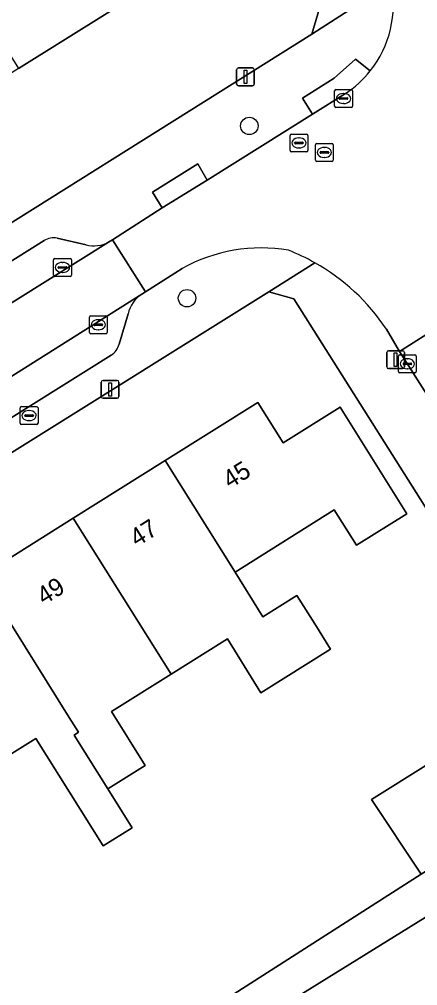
# Model space of a CAD drawing. Extents: x 159352 to 160617, y 385888 to 387323.
# Drawn here: x 159710.7 to 159733, y 386029 to 386083.1 of the extents above; entities that cross this region are included whole.
import ezdxf

# ---------------------------------------------------------------- set-up
doc = ezdxf.new("R2010")
doc.units = 0
for name, color, linetype in [('IMGEO_Boom', 7, 'Continuous'), ('IMGEO_Brandkraan', 7, 'Continuous'), ('IMGEO_Erf', 7, 'Continuous'), ('IMGEO_Kolk', 7, 'Continuous'), ('IMGEO_Lichtmast', 7, 'Continuous'), ('IMGEO_Muur', 7, 'Continuous'), ('IMGEO_Pand', 7, 'Continuous'), ('IMGEO_Pand_nummerreeks', 7, 'Continuous'), ('IMGEO_Parkeervlak_open', 7, 'Continuous'), ('IMGEO_Rijbaan_lokaal_open', 7, 'Continuous'), ('IMGEO_Rioolput', 7, 'Continuous'), ('IMGEO_Voetpad_open', 7, 'Continuous')]:
    doc.layers.add(name, color=color, linetype=linetype)

msp = doc.modelspace()

# ---------------------------------------------------------------- linework, layer by layer
at = {"layer": 'IMGEO_Boom'}
for centre in [(159723.56, 386077.111), (159720.07, 386067.462)]:
    msp.add_circle(centre, 0.489, dxfattribs=at)
at = {"layer": 'IMGEO_Brandkraan'}
for p, q in [((159710.714, 386060.464), (159710.714, 386061.316)), ((159710.789, 386061.39), (159711.641, 386061.39)), ((159711.715, 386061.316), (159711.715, 386060.464)), ((159710.973, 386060.884), (159710.973, 386060.896)), ((159711.411, 386060.847), (159711.013, 386060.847)), ((159711.016, 386060.933), (159711.414, 386060.933)), ((159711.202, 386061.17), (159711.227, 386061.17)), ((159711.457, 386060.896), (159711.457, 386060.884)), ((159711.641, 386060.39), (159710.789, 386060.39)), ((159711.225, 386060.61), (159711.2, 386060.61))]:
    msp.add_line(p, q, dxfattribs=at)
for points in [[(159710.714, 386060.464), (159710.714, 386061.316)], [(159710.789, 386061.39), (159711.641, 386061.39)], [(159711.715, 386061.316), (159711.715, 386060.464)], [(159711.641, 386060.39), (159710.789, 386060.39)]]:
    msp.add_lwpolyline(points, dxfattribs=at)
for centre, radius, start, end in [((159710.791, 386061.314), 0.0765, 91.552, 178.448), ((159710.791, 386061.314), 0.0765, 91.552, 178.448), ((159711.639, 386061.314), 0.0765, 1.552, 88.448), ((159711.639, 386061.314), 0.0765, 1.552, 88.448), ((159711.013, 386060.893), 0.0403, 85.8775, 175.7526), ((159711.01, 386060.883), 0.0366, 178.938, 274.7102), ((159711.414, 386060.89), 0.043, 264.8664, 352.4533), ((159711.418, 386060.895), 0.0386, 1.7309, 96.639), ((159710.791, 386060.466), 0.0765, 181.552, 268.448), ((159710.791, 386060.466), 0.0765, 181.552, 268.448), ((159711.639, 386060.466), 0.0765, 271.552, 358.448), ((159711.639, 386060.466), 0.0765, 271.552, 358.448)]:
    msp.add_arc(centre, radius, start, end, dxfattribs=at)
for centre, major_axis, ratio, start_param, end_param in [((159711.201, 386060.89), (-0.387, 0.002), 0.722429, 4.712389, 7.853982), ((159711.226, 386060.89), (-0.39, 0.002), 0.717154, 1.570796, 4.712389)]:
    msp.add_ellipse(centre, major_axis=major_axis, ratio=ratio, start_param=start_param, end_param=end_param, dxfattribs=at)
at = {"layer": 'IMGEO_Erf'}
for points in [[(159682.021, 386086.971), (159675.765, 386083.062), (159677.645, 386080.051), (159675.693, 386078.833), (159673.743, 386077.616), (159671.864, 386080.628), (159664.171, 386075.803), (159675.622, 386057.544), (159678.147, 386053.368), (159680.364, 386052.973), (159727.06, 386082.254), (159727.834, 386084.857)], [(159715.741, 386083.528), (159710.62, 386080.324), (159705.257, 386076.97), (159700.341, 386073.894), (159694.987, 386070.545), (159689.802, 386067.302), (159684.835, 386064.194), (159679.316, 386060.742), (159677.344, 386063.895), (159674.183, 386061.917), (159668.443, 386071.26), (159671.836, 386073.379), (159671.913, 386073.256), (159673.873, 386070.118), (159679.098, 386073.381), (159679.277, 386073.094), (159684.247, 386076.198), (159689.434, 386079.437), (159694.775, 386082.772), (159696.55, 386079.963), (159701.469, 386083.035), (159701.464, 386083.043), (159699.747, 386085.796)], [(159708.502, 386051.905), (159713.682, 386055.143), (159718.85, 386058.374), (159724.039, 386061.618), (159725.451, 386059.359), (159728.653, 386061.361), (159732.387, 386055.393), (159729.564, 386053.627), (159728.326, 386055.605), (159722.758, 386052.122), (159724.32, 386049.624), (159726.229, 386050.819), (159727.228, 386049.223), (159728.112, 386047.81), (159724.213, 386045.369), (159722.329, 386048.377), (159719.171, 386046.4), (159715.841, 386044.315), (159717.73, 386041.298), (159715.63, 386039.982), (159716.992, 386037.806), (159715.372, 386036.791), (159711.6, 386042.813), (159708.294, 386040.745)]]:
    msp.add_lwpolyline(points, dxfattribs=at)
msp.add_lwpolyline([(159733.186, 386035.211), (159730.405, 386039.383), (159739.998, 386045.377), (159726.053, 386067.427), (159724.652, 386067.823), (159682.76, 386041.661), (159677.195, 386038.177), (159676.499, 386035.726), (159692.861, 386009.756), (159693.588, 386010.224), (159695.905, 386011.714), (159692.99, 386016.431), (159699.422, 386020.406), (159702.337, 386015.688), (159707.722, 386019.015), (159705.988, 386021.823), (159710.701, 386024.734), (159712.435, 386021.927)], close=True, dxfattribs=at)
at = {"layer": 'IMGEO_Kolk'}
for p, q in [((159728.418, 386079.147), (159729.27, 386079.147)), ((159728.343, 386078.221), (159728.343, 386079.073)), ((159728.602, 386078.641), (159728.602, 386078.653)), ((159729.04, 386078.604), (159728.642, 386078.604)), ((159728.645, 386078.69), (159729.043, 386078.69)), ((159728.831, 386078.927), (159728.856, 386078.927)), ((159729.086, 386078.653), (159729.086, 386078.641)), ((159729.344, 386079.073), (159729.344, 386078.221)), ((159729.27, 386078.147), (159728.418, 386078.147)), ((159728.854, 386078.367), (159728.829, 386078.367)), ((159712.586, 386068.76), (159712.586, 386069.612)), ((159712.661, 386069.686), (159713.513, 386069.686)), ((159713.074, 386069.466), (159713.099, 386069.466)), ((159713.587, 386069.612), (159713.587, 386068.76)), ((159712.845, 386069.18), (159712.845, 386069.192)), ((159713.283, 386069.143), (159712.885, 386069.143)), ((159712.888, 386069.229), (159713.286, 386069.229)), ((159713.097, 386068.906), (159713.072, 386068.906)), ((159713.329, 386069.192), (159713.329, 386069.18)), ((159713.513, 386068.686), (159712.661, 386068.686)), ((159714.595, 386065.55), (159714.595, 386066.402)), ((159714.67, 386066.476), (159715.522, 386066.476)), ((159715.083, 386066.256), (159715.108, 386066.256)), ((159715.596, 386066.402), (159715.596, 386065.55)), ((159714.854, 386065.97), (159714.854, 386065.982)), ((159715.292, 386065.933), (159714.894, 386065.933)), ((159714.897, 386066.019), (159715.295, 386066.019)), ((159715.106, 386065.696), (159715.081, 386065.696)), ((159715.338, 386065.982), (159715.338, 386065.97)), ((159715.522, 386065.476), (159714.67, 386065.476)), ((159731.919, 386063.363), (159731.919, 386064.215)), ((159731.994, 386064.289), (159732.846, 386064.289)), ((159732.407, 386064.069), (159732.432, 386064.069)), ((159732.92, 386064.215), (159732.92, 386063.363)), ((159732.178, 386063.783), (159732.178, 386063.795)), ((159732.616, 386063.746), (159732.218, 386063.746)), ((159732.221, 386063.832), (159732.619, 386063.832)), ((159732.43, 386063.509), (159732.405, 386063.509)), ((159732.662, 386063.795), (159732.662, 386063.783)), ((159732.846, 386063.289), (159731.994, 386063.289))]:
    msp.add_line(p, q, dxfattribs=at)
for points in [[(159728.418, 386079.147), (159729.27, 386079.147)], [(159728.343, 386078.221), (159728.343, 386079.073)], [(159729.344, 386079.073), (159729.344, 386078.221)], [(159729.27, 386078.147), (159728.418, 386078.147)], [(159712.586, 386068.76), (159712.586, 386069.612)], [(159712.661, 386069.686), (159713.513, 386069.686)], [(159713.587, 386069.612), (159713.587, 386068.76)], [(159713.513, 386068.686), (159712.661, 386068.686)], [(159714.595, 386065.55), (159714.595, 386066.402)], [(159714.67, 386066.476), (159715.522, 386066.476)], [(159715.596, 386066.402), (159715.596, 386065.55)], [(159715.522, 386065.476), (159714.67, 386065.476)], [(159731.919, 386063.363), (159731.919, 386064.215)], [(159731.994, 386064.289), (159732.846, 386064.289)], [(159732.92, 386064.215), (159732.92, 386063.363)], [(159732.846, 386063.289), (159731.994, 386063.289)]]:
    msp.add_lwpolyline(points, dxfattribs=at)
for centre, radius, start, end in [((159728.42, 386079.071), 0.0765, 91.552, 178.448), ((159728.42, 386079.071), 0.0765, 91.552, 178.448), ((159729.268, 386079.071), 0.0765, 1.552, 88.448), ((159729.268, 386079.071), 0.0765, 1.552, 88.448), ((159728.642, 386078.65), 0.0403, 85.8775, 175.7526), ((159728.639, 386078.64), 0.0366, 178.938, 274.7102), ((159729.043, 386078.647), 0.043, 264.8664, 352.4533), ((159729.047, 386078.652), 0.0386, 1.7309, 96.639), ((159728.42, 386078.223), 0.0765, 181.552, 268.448), ((159728.42, 386078.223), 0.0765, 181.552, 268.448), ((159729.268, 386078.223), 0.0765, 271.552, 358.448), ((159729.268, 386078.223), 0.0765, 271.552, 358.448), ((159712.663, 386069.61), 0.0765, 91.552, 178.448), ((159712.663, 386069.61), 0.0765, 91.552, 178.448), ((159713.511, 386069.61), 0.0765, 1.552, 88.448), ((159713.511, 386069.61), 0.0765, 1.552, 88.448), ((159712.885, 386069.189), 0.0403, 85.8775, 175.7526), ((159712.882, 386069.179), 0.0366, 178.938, 274.7102), ((159713.286, 386069.186), 0.043, 264.8664, 352.4533), ((159713.29, 386069.191), 0.0386, 1.7309, 96.639), ((159712.663, 386068.762), 0.0765, 181.552, 268.448), ((159712.663, 386068.762), 0.0765, 181.552, 268.448), ((159713.511, 386068.762), 0.0765, 271.552, 358.448), ((159713.511, 386068.762), 0.0765, 271.552, 358.448), ((159714.672, 386066.4), 0.0765, 91.552, 178.448), ((159714.672, 386066.4), 0.0765, 91.552, 178.448), ((159715.52, 386066.4), 0.0765, 1.552, 88.448), ((159715.52, 386066.4), 0.0765, 1.552, 88.448), ((159714.894, 386065.979), 0.0403, 85.8775, 175.7526), ((159714.891, 386065.969), 0.0366, 178.938, 274.7102), ((159715.295, 386065.976), 0.043, 264.8664, 352.4533), ((159715.299, 386065.981), 0.0386, 1.7309, 96.639), ((159714.672, 386065.552), 0.0765, 181.552, 268.448), ((159714.672, 386065.552), 0.0765, 181.552, 268.448), ((159715.52, 386065.552), 0.0765, 271.552, 358.448), ((159715.52, 386065.552), 0.0765, 271.552, 358.448), ((159731.996, 386064.213), 0.0765, 91.552, 178.448), ((159731.996, 386064.213), 0.0765, 91.552, 178.448), ((159732.844, 386064.213), 0.0765, 1.552, 88.448), ((159732.844, 386064.213), 0.0765, 1.552, 88.448), ((159732.218, 386063.792), 0.0403, 85.8775, 175.7526), ((159732.215, 386063.782), 0.0366, 178.938, 274.7102), ((159732.619, 386063.789), 0.043, 264.8664, 352.4533), ((159732.623, 386063.794), 0.0386, 1.7309, 96.639), ((159731.996, 386063.365), 0.0765, 181.552, 268.448), ((159731.996, 386063.365), 0.0765, 181.552, 268.448), ((159732.844, 386063.365), 0.0765, 271.552, 358.448), ((159732.844, 386063.365), 0.0765, 271.552, 358.448)]:
    msp.add_arc(centre, radius, start, end, dxfattribs=at)
for centre, major_axis, ratio, start_param, end_param in [((159728.83, 386078.647), (-0.387, 0.002), 0.722429, 4.712389, 7.853982), ((159728.855, 386078.647), (-0.39, 0.002), 0.717154, 1.570796, 4.712389), ((159713.073, 386069.186), (-0.387, 0.002), 0.722429, 4.712389, 7.853982), ((159713.098, 386069.186), (-0.39, 0.002), 0.717154, 1.570796, 4.712389), ((159715.082, 386065.976), (-0.387, 0.002), 0.722429, 4.712389, 7.853982), ((159715.107, 386065.976), (-0.39, 0.002), 0.717154, 1.570796, 4.712389), ((159732.406, 386063.789), (-0.387, 0.002), 0.722429, 4.712389, 7.853982), ((159732.431, 386063.789), (-0.39, 0.002), 0.717154, 1.570796, 4.712389)]:
    msp.add_ellipse(centre, major_axis=major_axis, ratio=ratio, start_param=start_param, end_param=end_param, dxfattribs=at)
at = {"layer": 'IMGEO_Lichtmast'}
for p, q in [((159722.845, 386079.457), (159722.845, 386080.257)), ((159722.845, 386080.257), (159722.845, 386079.457)), ((159722.945, 386080.357), (159723.735, 386080.357)), ((159723.735, 386080.357), (159722.945, 386080.357)), ((159723.835, 386080.257), (159723.835, 386079.457)), ((159723.835, 386079.457), (159723.835, 386080.257)), ((159723.735, 386079.357), (159722.945, 386079.357)), ((159722.945, 386079.357), (159723.735, 386079.357)), ((159731.36, 386064.52), (159732.15, 386064.52)), ((159732.15, 386064.52), (159731.36, 386064.52)), ((159731.26, 386063.62), (159731.26, 386064.42)), ((159731.26, 386064.42), (159731.26, 386063.62)), ((159732.25, 386064.42), (159732.25, 386063.62)), ((159732.25, 386063.62), (159732.25, 386064.42)), ((159732.15, 386063.52), (159731.36, 386063.52)), ((159731.36, 386063.52), (159732.15, 386063.52)), ((159715.365, 386062.857), (159716.155, 386062.857)), ((159716.155, 386062.857), (159715.365, 386062.857)), ((159715.265, 386061.957), (159715.265, 386062.757)), ((159715.265, 386062.757), (159715.265, 386061.957)), ((159716.255, 386062.757), (159716.255, 386061.957)), ((159716.255, 386061.957), (159716.255, 386062.757)), ((159716.155, 386061.857), (159715.365, 386061.857)), ((159715.365, 386061.857), (159716.155, 386061.857))]:
    msp.add_line(p, q, dxfattribs=at)
for points in [[(159723.265, 386080.232), (159723.415, 386080.232), (159723.415, 386079.482), (159723.265, 386079.482), (159723.265, 386080.232)], [(159731.68, 386064.395), (159731.83, 386064.395), (159731.83, 386063.645), (159731.68, 386063.645), (159731.68, 386064.395)], [(159715.685, 386062.732), (159715.835, 386062.732), (159715.835, 386061.982), (159715.685, 386061.982), (159715.685, 386062.732)]]:
    msp.add_lwpolyline(points, dxfattribs=at)
for centre, start, end in [((159722.945, 386080.257), 90, 180), ((159722.945, 386080.257), 90, 180), ((159723.735, 386080.257), 0, 90), ((159723.735, 386080.257), 360, 90), ((159722.945, 386079.457), 180, 270), ((159722.945, 386079.457), 180, 270), ((159723.735, 386079.457), 270, 0), ((159723.735, 386079.457), 270, 0), ((159731.36, 386064.42), 90, 180), ((159731.36, 386064.42), 90, 180), ((159732.15, 386064.42), 0, 90), ((159732.15, 386064.42), 360, 90), ((159731.36, 386063.62), 180, 270), ((159731.36, 386063.62), 180, 270), ((159732.15, 386063.62), 270, 0), ((159732.15, 386063.62), 270, 0), ((159715.365, 386062.757), 90, 180), ((159715.365, 386062.757), 90, 180), ((159716.155, 386062.757), 0, 90), ((159716.155, 386062.757), 360, 90), ((159715.365, 386061.957), 180, 270), ((159715.365, 386061.957), 180, 270), ((159716.155, 386061.957), 270, 0), ((159716.155, 386061.957), 270, 0)]:
    msp.add_arc(centre, 0.1, start, end, dxfattribs=at)
at = {"layer": 'IMGEO_Muur'}
msp.add_lwpolyline([(159739.998, 386045.377), (159726.053, 386067.427)], dxfattribs=at)
at = {"layer": 'IMGEO_Pand'}
for points in [[(159710.256, 386092.311), (159705.178, 386089.14), (159705.249, 386089.026), (159706.834, 386086.386), (159710.62, 386080.324), (159715.741, 386083.528)], [(159722.758, 386052.122), (159728.326, 386055.605), (159729.564, 386053.627), (159732.387, 386055.393), (159728.653, 386061.361), (159725.451, 386059.359), (159724.039, 386061.618), (159718.85, 386058.374)], [(159724.32, 386049.624), (159722.758, 386052.122), (159718.85, 386058.374), (159713.682, 386055.143), (159719.171, 386046.4), (159722.329, 386048.377), (159724.213, 386045.369), (159728.112, 386047.81), (159727.228, 386049.223), (159726.229, 386050.819)], [(159713.682, 386055.143), (159708.502, 386051.905), (159713.466, 386043.98), (159713.984, 386043.152), (159713.74, 386042.999), (159715.63, 386039.982), (159717.73, 386041.298), (159715.841, 386044.315), (159719.171, 386046.4)], [(159708.502, 386051.905), (159703.328, 386048.671), (159707.246, 386042.417), (159708.294, 386040.745), (159711.6, 386042.813), (159715.372, 386036.791), (159716.992, 386037.806), (159715.63, 386039.982), (159713.74, 386042.999), (159713.984, 386043.152), (159713.466, 386043.98)], [(159739.998, 386045.377), (159730.405, 386039.383), (159733.186, 386035.211), (159742.641, 386041.129)]]:
    msp.add_lwpolyline(points, close=True, dxfattribs=at)
at = {"layer": 'IMGEO_Parkeervlak_open'}
for points in [[(159684.747, 386051.268), (159715.668, 386070.601)], [(159712.06, 386070.688), (159686.23, 386054.518)], [(159714.408, 386070.453), (159712.791, 386070.822)], [(159717.543, 386067.695), (159686.194, 386047.956), (159678.382, 386043.037)], [(159716.265, 386064.895), (159716.765, 386066.587)], [(159681.467, 386042.865), (159702.746, 386056.105), (159715.811, 386064.272)]]:
    msp.add_lwpolyline(points, dxfattribs=at)
for centre, radius, start, end in [((159712.594, 386069.835), 1.006, 78.7215, 122.0536), ((159714.846, 386072.164), 1.766, 255.6525, 297.7461), ((159718.52, 386066.182), 1.801, 122.8468, 167.0028), ((159715.242, 386065.164), 1.058, 302.5514, 345.2845)]:
    msp.add_arc(centre, radius, start, end, dxfattribs=at)
at = {"layer": 'IMGEO_Rijbaan_lokaal_open'}
for points in [[(159728.944, 386078.921), (159727.099, 386077.762), (159721.197, 386074.077), (159718.676, 386072.526), (159715.89, 386070.74), (159717.747, 386067.827), (159719.799, 386069.131)], [(159731.248, 386065.731), (159731.979, 386064.484), (159735.815, 386066.908), (159735.069, 386068.094), (159734.553, 386068.939)]]:
    msp.add_lwpolyline(points, dxfattribs=at)
for points in [[(159684.747, 386051.268), (159684.308, 386050.988), (159686.194, 386047.956), (159717.543, 386067.695), (159717.747, 386067.827), (159715.89, 386070.74), (159715.668, 386070.601)], [(159731.979, 386064.484), (159734.907, 386059.872), (159741.407, 386049.679), (159742.601, 386047.804), (159749.546, 386036.81), (159750.194, 386035.775), (159752.658, 386031.759), (159756.838, 386034.337), (159755.487, 386036.469), (159749.673, 386045.484), (159747.883, 386048.224), (159745.179, 386052.371), (159735.815, 386066.908)], [(159746.307, 386035.207), (159743.822, 386039.222), (159711.277, 386019.075), (159712.358, 386017.329), (159713.852, 386014.956), (159720.831, 386019.35), (159722.112, 386020.156), (159728.436, 386024.138), (159729.047, 386024.522)]]:
    msp.add_lwpolyline(points, close=True, dxfattribs=at)
for centre, radius, start, end in [((159725.699, 386083.892), 5.933, 321.4994, 11.9611), ((159725.747, 386083.822), 5.851, 303.1174, 321.7474), ((159724.231, 386061.115), 9.16, 80.4279, 118.9364), ((159721.43, 386059.092), 11.87, 60.7399, 68.6378), ((159721.478, 386059.203), 11.751, 33.7497, 60.6789)]:
    msp.add_arc(centre, radius, start, end, dxfattribs=at)
at = {"layer": 'IMGEO_Rioolput'}
for p, q in [((159725.841, 386075.732), (159725.841, 386076.584)), ((159725.916, 386076.658), (159726.768, 386076.658)), ((159726.329, 386076.438), (159726.354, 386076.438)), ((159726.842, 386076.584), (159726.842, 386075.732)), ((159726.1, 386076.152), (159726.1, 386076.164)), ((159726.538, 386076.115), (159726.14, 386076.115)), ((159726.143, 386076.201), (159726.541, 386076.201)), ((159726.352, 386075.878), (159726.327, 386075.878)), ((159726.584, 386076.164), (159726.584, 386076.152)), ((159727.267, 386075.201), (159727.267, 386076.053)), ((159727.342, 386076.127), (159728.194, 386076.127)), ((159727.755, 386075.907), (159727.78, 386075.907)), ((159728.268, 386076.053), (159728.268, 386075.201)), ((159726.768, 386075.658), (159725.916, 386075.658)), ((159727.526, 386075.621), (159727.526, 386075.633)), ((159727.964, 386075.584), (159727.566, 386075.584)), ((159727.569, 386075.67), (159727.967, 386075.67)), ((159727.778, 386075.347), (159727.753, 386075.347)), ((159728.01, 386075.633), (159728.01, 386075.621)), ((159728.194, 386075.127), (159727.342, 386075.127))]:
    msp.add_line(p, q, dxfattribs=at)
for points in [[(159725.841, 386075.732), (159725.841, 386076.584)], [(159725.916, 386076.658), (159726.768, 386076.658)], [(159726.842, 386076.584), (159726.842, 386075.732)], [(159727.267, 386075.201), (159727.267, 386076.053)], [(159727.342, 386076.127), (159728.194, 386076.127)], [(159728.268, 386076.053), (159728.268, 386075.201)], [(159726.768, 386075.658), (159725.916, 386075.658)], [(159728.194, 386075.127), (159727.342, 386075.127)]]:
    msp.add_lwpolyline(points, dxfattribs=at)
for centre, radius, start, end in [((159725.918, 386076.582), 0.0765, 91.552, 178.448), ((159725.918, 386076.582), 0.0765, 91.552, 178.448), ((159726.766, 386076.582), 0.0765, 1.552, 88.448), ((159726.766, 386076.582), 0.0765, 1.552, 88.448), ((159726.14, 386076.161), 0.0403, 85.8775, 175.7526), ((159726.137, 386076.151), 0.0366, 178.938, 274.7102), ((159726.541, 386076.158), 0.043, 264.8664, 352.4533), ((159726.545, 386076.163), 0.0386, 1.7309, 96.639), ((159727.344, 386076.051), 0.0765, 91.552, 178.448), ((159727.344, 386076.051), 0.0765, 91.552, 178.448), ((159728.192, 386076.051), 0.0765, 1.552, 88.448), ((159728.192, 386076.051), 0.0765, 1.552, 88.448), ((159725.918, 386075.734), 0.0765, 181.552, 268.448), ((159725.918, 386075.734), 0.0765, 181.552, 268.448), ((159726.766, 386075.734), 0.0765, 271.552, 358.448), ((159726.766, 386075.734), 0.0765, 271.552, 358.448), ((159727.566, 386075.63), 0.0403, 85.8775, 175.7526), ((159727.563, 386075.62), 0.0366, 178.938, 274.7102), ((159727.967, 386075.627), 0.043, 264.8664, 352.4533), ((159727.971, 386075.632), 0.0386, 1.7309, 96.639), ((159727.344, 386075.203), 0.0765, 181.552, 268.448), ((159727.344, 386075.203), 0.0765, 181.552, 268.448), ((159728.192, 386075.203), 0.0765, 271.552, 358.448), ((159728.192, 386075.203), 0.0765, 271.552, 358.448)]:
    msp.add_arc(centre, radius, start, end, dxfattribs=at)
for centre, major_axis, ratio, start_param, end_param in [((159726.328, 386076.158), (-0.387, 0.002), 0.722429, 4.712389, 7.853982), ((159726.353, 386076.158), (-0.39, 0.002), 0.717154, 1.570796, 4.712389), ((159727.754, 386075.627), (-0.387, 0.002), 0.722429, 4.712389, 7.853982), ((159727.779, 386075.627), (-0.39, 0.002), 0.717154, 1.570796, 4.712389)]:
    msp.add_ellipse(centre, major_axis=major_axis, ratio=ratio, start_param=start_param, end_param=end_param, dxfattribs=at)
at = {"layer": 'IMGEO_Voetpad_open'}
for points in [[(159678.601, 386168.796), (159674.448, 386166.054), (159677.208, 386165.677), (159712.934, 386108.61), (159713.923, 386107.031), (159717.083, 386101.983), (159727.834, 386084.857), (159727.06, 386082.254), (159731.503, 386085.122)], [(159731.503, 386085.122), (159727.06, 386082.254), (159680.364, 386052.973), (159675.699, 386050.365)], [(159720.667, 386074.995), (159721.197, 386074.077), (159727.099, 386077.762), (159726.537, 386078.662), (159728.317, 386079.78), (159729.51, 386080.849), (159730.342, 386080.199)], [(159730.342, 386080.199), (159729.51, 386080.849), (159728.317, 386079.78), (159726.537, 386078.662), (159727.099, 386077.762), (159728.944, 386078.921)], [(159715.668, 386070.601), (159715.89, 386070.74), (159718.676, 386072.526), (159718.131, 386073.409), (159720.667, 386074.995)], [(159686.23, 386054.518), (159712.06, 386070.688)], [(159712.791, 386070.822), (159714.408, 386070.453)], [(159727.232, 386069.448), (159724.652, 386067.823), (159726.053, 386067.427), (159739.998, 386045.377), (159742.641, 386041.129), (159743.822, 386039.222), (159746.307, 386035.207), (159771.719, 385994.399), (159773.833, 385991.005), (159785.861, 385971.689), (159788.912, 385973.68), (159788.6, 385974.171), (159788.248, 385974.74)], [(159724.652, 386067.823), (159727.232, 386069.448)], [(159719.799, 386069.131), (159717.747, 386067.827), (159717.543, 386067.695)], [(159674.294, 386034.404), (159676.499, 386035.726), (159677.195, 386038.177), (159682.76, 386041.661), (159724.652, 386067.823)], [(159716.765, 386066.587), (159716.265, 386064.895)], [(159734.907, 386059.872), (159731.979, 386064.484), (159731.248, 386065.731)], [(159715.811, 386064.272), (159702.746, 386056.105), (159681.467, 386042.865)]]:
    msp.add_lwpolyline(points, dxfattribs=at)
for points in [[(159718.676, 386072.526), (159721.197, 386074.077), (159720.667, 386074.995), (159718.131, 386073.409)], [(159743.822, 386039.222), (159742.641, 386041.129), (159733.186, 386035.211), (159712.435, 386021.927), (159707.722, 386019.015), (159702.337, 386015.688), (159695.905, 386011.714), (159693.588, 386010.224), (159694.532, 386008.709), (159711.277, 386019.075)]]:
    msp.add_lwpolyline(points, close=True, dxfattribs=at)
for centre, radius, start, end in [((159725.699, 386083.892), 5.933, 321.4994, 11.9611), ((159725.747, 386083.822), 5.851, 303.1174, 321.7474), ((159712.594, 386069.835), 1.006, 78.7215, 122.0536), ((159714.846, 386072.164), 1.766, 255.6525, 297.7461), ((159724.231, 386061.115), 9.16, 80.4279, 118.9364), ((159721.43, 386059.092), 11.87, 60.7399, 68.6378), ((159721.478, 386059.203), 11.751, 33.7497, 60.6789), ((159718.52, 386066.182), 1.801, 122.8468, 167.0028), ((159715.242, 386065.164), 1.058, 302.5514, 345.2845)]:
    msp.add_arc(centre, radius, start, end, dxfattribs=at)

# ---------------------------------------------------------------- texts
at = {"layer": 'IMGEO_Pand_nummerreeks'}
for s, p in [('45', (159722.472, 386056.77)), ('47', (159717.261, 386053.513)), ('49', (159712.05, 386050.256))]:
    msp.add_text(s, height=1, rotation=32.0112, dxfattribs=at).set_placement(p)

doc.saveas('drawing.dxf')
